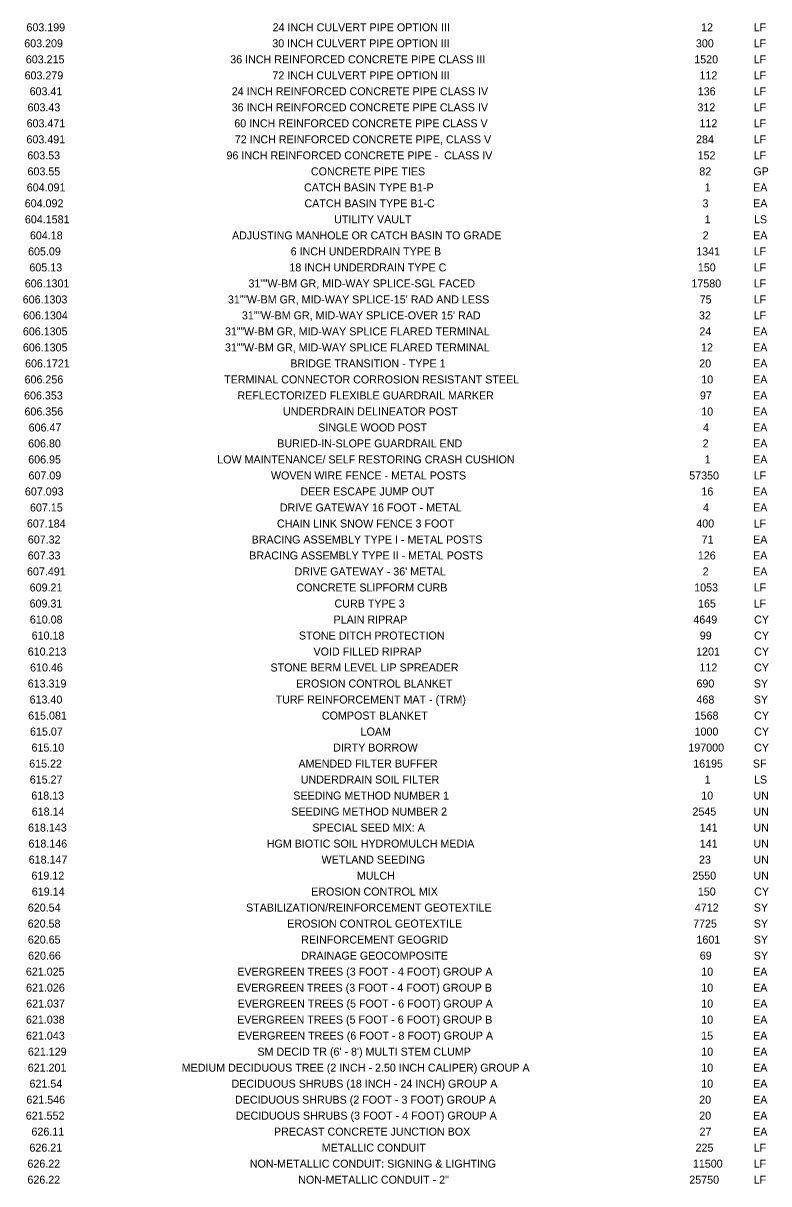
# Model space of a CAD drawing. Extents: x -18.7 to 5.6, y -2.7 to 4.
# Drawn here: x -18.674 to -17.757, y -0.273 to 1.155 of the extents above; entities that cross this region are included whole.
import ezdxf

# ---------------------------------------------------------------- set-up
doc = ezdxf.new("R2010")
doc.units = 0
doc.layers.add('ANNOTATION', color=7, linetype='Continuous')

msp = doc.modelspace()

# ---------------------------------------------------------------- texts
at = {"layer": 'ANNOTATION'}
for s, height, p in [('603.199', 0.00984, (-18.6697, 1.1446)), ('24 INCH CULVERT PIPE OPTION III', 0.009843, (-18.367, 1.1446)), ('12', 0.00984, (-17.8401, 1.1446)), ('LF', 0.00984, (-17.7755, 1.1446)), ('603.209', 0.00984, (-18.6724, 1.1249)), ('30 INCH CULVERT PIPE OPTION III', 0.009843, (-18.3674, 1.1249)), ('300', 0.00984, (-17.8465, 1.1249)), ('LF', 0.00984, (-17.7755, 1.1249)), ('603.215', 0.00984, (-18.6705, 1.1052)), ('36 INCH REINFORCED CONCRETE PIPE CLASS III', 0.009843, (-18.4191, 1.1052)), ('1520', 0.00984, (-17.8485, 1.1052)), ('LF', 0.00984, (-17.7755, 1.1052)), ('603.279', 0.00984, (-18.672, 1.0855)), ('72 INCH CULVERT PIPE OPTION III', 0.009843, (-18.3673, 1.0855)), ('112', 0.00984, (-17.8421, 1.0855)), ('LF', 0.00984, (-17.7755, 1.0855)), ('603.41', 0.00984, (-18.6658, 1.0659)), ('24 INCH REINFORCED CONCRETE PIPE CLASS IV', 0.009843, (-18.4172, 1.0659)), ('136', 0.00984, (-17.8442, 1.0659)), ('LF', 0.00984, (-17.7755, 1.0659)), ('603.43', 0.00984, (-18.6683, 1.0462)), ('36 INCH REINFORCED CONCRETE PIPE CLASS IV', 0.009843, (-18.4173, 1.0462)), ('312', 0.00984, (-17.8446, 1.0462)), ('LF', 0.00984, (-17.7755, 1.0462)), ('603.471', 0.00984, (-18.6695, 1.0265)), ('60 INCH REINFORCED CONCRETE PIPE CLASS V', 0.009843, (-18.4141, 1.0265)), ('112', 0.00984, (-17.8421, 1.0265)), ('LF', 0.00984, (-17.7755, 1.0265)), ('603.491', 0.00984, (-18.6697, 1.0068)), ('72 INCH REINFORCED CONCRETE PIPE, CLASS V', 0.009843, (-18.4135, 1.0068)), ('284', 0.00984, (-17.8463, 1.0068)), ('LF', 0.00984, (-17.7755, 1.0068)), ('603.53', 0.00984, (-18.6686, 0.9871)), ('96 INCH REINFORCED CONCRETE PIPE -  CLASS IV', 0.009843, (-18.4237, 0.9871)), ('152', 0.00984, (-17.8444, 0.9871)), ('LF', 0.00984, (-17.7755, 0.9871)), ('603.55', 0.00984, (-18.6684, 0.9674)), ('CONCRETE PIPE TIES', 0.009843, (-18.3199, 0.9674)), ('82', 0.00984, (-17.8423, 0.9674)), ('GP', 0.00984, (-17.7759, 0.9674)), ('604.091', 0.00984, (-18.6693, 0.9477)), ('CATCH BASIN TYPE B1-P', 0.009843, (-18.3284, 0.9477)), ('1', 0.00984, (-17.8358, 0.9477)), ('EA', 0.00984, (-17.7761, 0.9477)), ('604.092', 0.00984, (-18.6718, 0.9281)), ('CATCH BASIN TYPE B1-C', 0.009843, (-18.3278, 0.9281)), ('3', 0.00984, (-17.8383, 0.9281)), ('EA', 0.00984, (-17.7761, 0.9281)), ('604.1581', 0.00984, (-18.6716, 0.9084)), ('UTILITY VAULT', 0.009843, (-18.2913, 0.9084)), ('1', 0.00984, (-17.8358, 0.9084)), ('LS', 0.00984, (-17.7751, 0.9084)), ('604.18', 0.00984, (-18.6654, 0.8887)), ('ADJUSTING MANHOLE OR CATCH BASIN TO GRADE', 0.009843, (-18.4169, 0.8887)), ('2', 0.00984, (-17.8382, 0.8887)), ('EA', 0.00984, (-17.7761, 0.8887)), ('605.09', 0.00984, (-18.6677, 0.869)), ('6 INCH UNDERDRAIN TYPE B', 0.009843, (-18.3448, 0.869)), ('1341', 0.00984, (-17.8461, 0.869)), ('LF', 0.00984, (-17.7755, 0.869)), ('605.13', 0.00984, (-18.6661, 0.8493)), ('18 INCH UNDERDRAIN TYPE C', 0.009843, (-18.3464, 0.8493)), ('150', 0.00984, (-17.8441, 0.8493)), ('LF', 0.00984, (-17.7755, 0.8493)), ('606.1301', 0.00984, (-18.6718, 0.8296)), ('31””W-BM GR, MID-WAY SPLICE-SGL FACED', 0.009843, (-18.3967, 0.8296)), ('17580', 0.00984, (-17.852, 0.8296)), ('LF', 0.00984, (-17.7755, 0.8296)), ('606.1303', 0.00984, (-18.6743, 0.8099)), ("31””W-BM GR, MID-WAY SPLICE-15' RAD AND LESS", 0.009843, (-18.422, 0.8099)), ('75', 0.00984, (-17.8418, 0.8099)), ('LF', 0.00984, (-17.7755, 0.8099)), ('606.1304', 0.00984, (-18.6738, 0.7903)), ("31””W-BM GR, MID-WAY SPLICE-OVER 15' RAD", 0.009843, (-18.4048, 0.7903)), ('32', 0.00984, (-17.8427, 0.7903)), ('LF', 0.00984, (-17.7755, 0.7903)), ('606.1305', 0.00984, (-18.6741, 0.7706)), ('31””W-BM GR, MID-WAY SPLICE FLARED TERMINAL', 0.009843, (-18.4256, 0.7706)), ('24', 0.00984, (-17.8422, 0.7706)), ('EA', 0.00984, (-17.7761, 0.7706)), ('606.1305', 0.00984, (-18.6741, 0.7509)), ('31””W-BM GR, MID-WAY SPLICE FLARED TERMINAL', 0.009843, (-18.4256, 0.7509)), ('12', 0.00984, (-17.8401, 0.7509)), ('EA', 0.00984, (-17.7761, 0.7509)), ('606.1721', 0.00984, (-18.6714, 0.7312)), ('BRIDGE TRANSITION - TYPE 1', 0.009843, (-18.3452, 0.7312)), ('20', 0.00984, (-17.8424, 0.7312)), ('EA', 0.00984, (-17.7761, 0.7312)), ('606.256', 0.00984, (-18.672, 0.7115)), ('TERMINAL CONNECTOR CORROSION RESISTANT STEEL', 0.009843, (-18.4266, 0.7115)), ('10', 0.00984, (-17.8399, 0.7115)), ('EA', 0.00984, (-17.7761, 0.7115)), ('606.353', 0.00984, (-18.6726, 0.6918)), ('REFLECTORIZED FLEXIBLE GUARDRAIL MARKER', 0.009843, (-18.4102, 0.6918)), ('97', 0.00984, (-17.8415, 0.6918)), ('EA', 0.00984, (-17.7761, 0.6918)), ('606.356', 0.00984, (-18.6721, 0.6721)), ('UNDERDRAIN DELINEATOR POST', 0.009843, (-18.3543, 0.6721)), ('10', 0.00984, (-17.8399, 0.6721)), ('EA', 0.00984, (-17.7761, 0.6721)), ('606.47', 0.00984, (-18.667, 0.6524)), ('SINGLE WOOD POST', 0.009843, (-18.3109, 0.6524)), ('4', 0.00984, (-17.8378, 0.6524)), ('EA', 0.00984, (-17.7761, 0.6524)), ('606.80', 0.00984, (-18.6676, 0.6328)), ('BURIED-IN-SLOPE GUARDRAIL END', 0.009843, (-18.3613, 0.6328)), ('2', 0.00984, (-17.8382, 0.6328)), ('EA', 0.00984, (-17.7761, 0.6328)), ('606.95', 0.00984, (-18.6675, 0.6131)), ('LOW MAINTENANCE/ SELF RESTORING CRASH CUSHION', 0.009843, (-18.4351, 0.6131)), ('1', 0.00984, (-17.8358, 0.6131)), ('EA', 0.00984, (-17.7761, 0.6131)), ('607.09', 0.00984, (-18.6672, 0.5934)), ('WOVEN WIRE FENCE - METAL POSTS', 0.009843, (-18.369, 0.5934)), ('57350', 0.00984, (-17.8547, 0.5934)), ('LF', 0.00984, (-17.7755, 0.5934)), ('607.093', 0.00984, (-18.6716, 0.5737)), ('DEER ESCAPE JUMP OUT', 0.009843, (-18.3329, 0.5737)), ('16', 0.00984, (-17.8397, 0.5737)), ('EA', 0.00984, (-17.7761, 0.5737)), ('607.15', 0.00984, (-18.6653, 0.554)), ('DRIVE GATEWAY 16 FOOT - METAL', 0.009843, (-18.3581, 0.554)), ('4', 0.00984, (-17.8378, 0.554)), ('EA', 0.00984, (-17.7761, 0.554)), ('607.184', 0.00984, (-18.6691, 0.5343)), ('CHAIN LINK SNOW FENCE 3 FOOT', 0.009843, (-18.3617, 0.5343)), ('400', 0.00984, (-17.846, 0.5343)), ('LF', 0.00984, (-17.7755, 0.5343)), ('607.32', 0.00984, (-18.668, 0.5146)), ('BRACING ASSEMBLY TYPE I - METAL POSTS', 0.009843, (-18.3928, 0.5146)), ('71', 0.00984, (-17.8395, 0.5146)), ('EA', 0.00984, (-17.7761, 0.5146)), ('607.33', 0.00984, (-18.6681, 0.495)), ('BRACING ASSEMBLY TYPE II - METAL POSTS', 0.009843, (-18.3957, 0.495)), ('126', 0.00984, (-17.8441, 0.495)), ('EA', 0.00984, (-17.7761, 0.495)), ('607.491', 0.00984, (-18.669, 0.4753)), ("DRIVE GATEWAY - 36' METAL", 0.009843, (-18.34, 0.4753)), ('2', 0.00984, (-17.8382, 0.4753)), ('EA', 0.00984, (-17.7761, 0.4753)), ('609.21', 0.00984, (-18.6657, 0.4556)), ('CONCRETE SLIPFORM CURB', 0.009843, (-18.3378, 0.4556)), ('1053', 0.00984, (-17.8486, 0.4556)), ('LF', 0.00984, (-17.7755, 0.4556)), ('609.31', 0.00984, (-18.6658, 0.4359)), ('CURB TYPE 3', 0.009843, (-18.2909, 0.4359)), ('165', 0.00984, (-17.8439, 0.4359)), ('LF', 0.00984, (-17.7755, 0.4359)), ('610.08', 0.00984, (-18.6655, 0.4162)), ('PLAIN RIPRAP', 0.009843, (-18.2921, 0.4162)), ('4649', 0.00984, (-17.8496, 0.4162)), ('CY', 0.00984, (-17.7749, 0.4162)), ('610.18', 0.00984, (-18.6633, 0.3965)), ('STONE DITCH PROTECTION', 0.009843, (-18.3347, 0.3965)), ('99', 0.00984, (-17.8417, 0.3965)), ('CY', 0.00984, (-17.7749, 0.3965)), ('610.213', 0.00984, (-18.6681, 0.3768)), ('VOID FILLED RIPRAP', 0.009843, (-18.3167, 0.3768)), ('1201', 0.00984, (-17.8462, 0.3768)), ('CY', 0.00984, (-17.7749, 0.3768)), ('610.46', 0.00984, (-18.6652, 0.3572)), ('STONE BERM LEVEL LIP SPREADER', 0.009843, (-18.3696, 0.3572)), ('112', 0.00984, (-17.8421, 0.3572)), ('CY', 0.00984, (-17.7749, 0.3572)), ('613.319', 0.00984, (-18.6681, 0.3375)), ('EROSION CONTROL BLANKET', 0.009843, (-18.3381, 0.3375)), ('690', 0.00984, (-17.8458, 0.3375)), ('SY', 0.00984, (-17.7753, 0.3375)), ('613.40', 0.00984, (-18.6658, 0.3178)), ('TURF REINFORCEMENT MAT - (TRM)', 0.009843, (-18.3633, 0.3178)), ('468', 0.00984, (-17.8458, 0.3178)), ('SY', 0.00984, (-17.7753, 0.3178)), ('615.081', 0.00984, (-18.6676, 0.2981)), ('COMPOST BLANKET', 0.009843, (-18.3064, 0.2981)), ('1568', 0.00984, (-17.848, 0.2981)), ('CY', 0.00984, (-17.7749, 0.2981)), ('615.07', 0.00984, (-18.6653, 0.2784)), ('LOAM', 0.00984, (-18.2588, 0.2784)), ('1000', 0.00984, (-17.8481, 0.2784)), ('CY', 0.00984, (-17.7749, 0.2784)), ('615.10', 0.00984, (-18.6635, 0.2587)), ('DIRTY BORROW', 0.009843, (-18.2925, 0.2587)), ('197000', 0.00984, (-17.8558, 0.2587)), ('CY', 0.00984, (-17.7749, 0.2587)), ('615.22', 0.00984, (-18.6663, 0.239)), ('AMENDED FILTER BUFFER ', 0.009843, (-18.3352, 0.239)), ('16195', 0.00984, (-17.8498, 0.239)), ('SF', 0.00984, (-17.7765, 0.239)), ('615.27', 0.00984, (-18.6656, 0.2194)), ('UNDERDRAIN SOIL FILTER', 0.009843, (-18.3324, 0.2194)), ('1', 0.00984, (-17.8358, 0.2194)), ('LS', 0.00984, (-17.7751, 0.2194)), ('618.13', 0.00984, (-18.6637, 0.1997)), ('SEEDING METHOD NUMBER 1', 0.009843, (-18.3416, 0.1997)), ('10', 0.00984, (-17.8399, 0.1997)), ('UN', 0.00984, (-17.7758, 0.1997)), ('618.14', 0.00984, (-18.6632, 0.18)), ('SEEDING METHOD NUMBER 2', 0.009843, (-18.3441, 0.18)), ('2545', 0.00984, (-17.8507, 0.18)), ('UN', 0.00984, (-17.7758, 0.18)), ('618.143', 0.00984, (-18.6677, 0.1603)), ('SPECIAL SEED MIX: A', 0.009843, (-18.3181, 0.1603)), ('141', 0.00984, (-17.8417, 0.1603)), ('UN', 0.00984, (-17.7758, 0.1603)), ('618.146', 0.00984, (-18.6672, 0.1406)), ('HGM BIOTIC SOIL HYDROMULCH MEDIA', 0.009843, (-18.3742, 0.1406)), ('141', 0.00984, (-17.8417, 0.1406)), ('UN', 0.00984, (-17.7758, 0.1406)), ('618.147', 0.00984, (-18.6669, 0.1209)), ('WETLAND SEEDING', 0.009843, (-18.3068, 0.1209)), ('23', 0.00984, (-17.8427, 0.1209)), ('UN', 0.00984, (-17.7758, 0.1209)), ('619.12', 0.00984, (-18.6635, 0.1012)), ('MULCH', 0.00984, (-18.2634, 0.1012)), ('2550', 0.00984, (-17.8509, 0.1012)), ('UN', 0.00984, (-17.7758, 0.1012)), ('619.14', 0.00984, (-18.6631, 0.0816)), ('EROSION CONTROL MIX', 0.009843, (-18.3196, 0.0816)), ('150', 0.00984, (-17.8441, 0.0816)), ('CY', 0.00984, (-17.7749, 0.0816)), ('620.54', 0.00984, (-18.668, 0.0619)), ('STABILIZATION/REINFORCEMENT GEOTEXTILE', 0.009843, (-18.3997, 0.0619)), ('4712', 0.00984, (-17.8478, 0.0619)), ('SY', 0.00984, (-17.7753, 0.0619)), ('620.58', 0.00984, (-18.6681, 0.0422)), ('EROSION CONTROL GEOTEXTILE', 0.009843, (-18.349, 0.0422)), ('7725', 0.00984, (-17.8499, 0.0422)), ('SY', 0.00984, (-17.7753, 0.0422)), ('620.65', 0.00984, (-18.668, 0.0225)), ('REINFORCEMENT GEOGRID', 0.009843, (-18.3318, 0.0225)), ('1601', 0.00984, (-17.8458, 0.0225)), ('SY', 0.00984, (-17.7753, 0.0225)), ('620.66', 0.00984, (-18.6677, 0.0028)), ('DRAINAGE GEOCOMPOSITE', 0.009843, (-18.3321, 0.0028)), ('69', 0.00984, (-17.8417, 0.0028)), ('SY', 0.00984, (-17.7753, 0.0028)), ('621.025', 0.00984, (-18.6704, -0.0169)), ('EVERGREEN TREES (3 FOOT - 4 FOOT) GROUP A', 0.009843, (-18.4104, -0.0169)), ('10', 0.00984, (-17.8399, -0.0169)), ('EA', 0.00984, (-17.7761, -0.0169)), ('621.026', 0.00984, (-18.6701, -0.0366)), ('EVERGREEN TREES (3 FOOT - 4 FOOT) GROUP B', 0.009843, (-18.411, -0.0366)), ('10', 0.00984, (-17.8399, -0.0366)), ('EA', 0.00984, (-17.7761, -0.0366)), ('621.037', 0.00984, (-18.67, -0.0562)), ('EVERGREEN TREES (5 FOOT - 6 FOOT) GROUP A', 0.009843, (-18.41, -0.0562)), ('10', 0.00984, (-17.8399, -0.0562)), ('EA', 0.00984, (-17.7761, -0.0562)), ('621.038', 0.00984, (-18.6703, -0.0759)), ('EVERGREEN TREES (5 FOOT - 6 FOOT) GROUP B', 0.009843, (-18.4106, -0.0759)), ('10', 0.00984, (-17.8399, -0.0759)), ('EA', 0.00984, (-17.7761, -0.0759)), ('621.043', 0.00984, (-18.6702, -0.0956)), ('EVERGREEN TREES (6 FOOT - 8 FOOT) GROUP A', 0.009843, (-18.4097, -0.0956)), ('15', 0.00984, (-17.84, -0.0956)), ('EA', 0.00984, (-17.7761, -0.0956)), ('621.129', 0.00984, (-18.6679, -0.1153)), ("SM DECID TR (6' - 8') MULTI STEM CLUMP", 0.009843, (-18.3857, -0.1153)), ('10', 0.00984, (-17.8399, -0.1153)), ('EA', 0.00984, (-17.7761, -0.1153)), ('621.201', 0.00984, (-18.6681, -0.135)), ('MEDIUM DECIDUOUS TREE (2 INCH - 2.50 INCH CALIPER) GROUP A', 0.009843, (-18.4788, -0.135)), ('10', 0.00984, (-17.8399, -0.135)), ('EA', 0.00984, (-17.7761, -0.135)), ('621.54', 0.00984, (-18.6659, -0.1547)), ('DECIDUOUS SHRUBS (18 INCH - 24 INCH) GROUP A', 0.009843, (-18.4175, -0.1547)), ('10', 0.00984, (-17.8399, -0.1547)), ('EA', 0.00984, (-17.7761, -0.1547)), ('621.546', 0.00984, (-18.6698, -0.1744)), ('DECIDUOUS SHRUBS (2 FOOT - 3 FOOT) GROUP A', 0.009843, (-18.4133, -0.1744)), ('20', 0.00984, (-17.8424, -0.1744)), ('EA', 0.00984, (-17.7761, -0.1744)), ('621.552', 0.00984, (-18.6705, -0.194)), ('DECIDUOUS SHRUBS (3 FOOT - 4 FOOT) GROUP A', 0.009843, (-18.4124, -0.194)), ('20', 0.00984, (-17.8424, -0.194)), ('EA', 0.00984, (-17.7761, -0.194)), ('626.11', 0.00984, (-18.6635, -0.2137)), ('PRECAST CONCRETE JUNCTION BOX', 0.009843, (-18.3653, -0.2137)), ('27', 0.00984, (-17.842, -0.2137)), ('EA', 0.00984, (-17.7761, -0.2137)), ('626.21', 0.00984, (-18.666, -0.2334)), ('METALLIC CONDUIT', 0.009843, (-18.3066, -0.2334)), ('225', 0.00984, (-17.8469, -0.2334)), ('LF', 0.00984, (-17.7755, -0.2334)), ('626.22', 0.00984, (-18.6685, -0.2531)), ('NON-METALLIC CONDUIT: SIGNING & LIGHTING', 0.009843, (-18.3951, -0.2531)), ('11500', 0.00984, (-17.8502, -0.2531)), ('LF', 0.00984, (-17.7755, -0.2531)), ('626.22', 0.00984, (-18.6685, -0.2728)), ('NON-METALLIC CONDUIT - 2"', 0.009843, (-18.3355, -0.2728)), ('25750', 0.00984, (-17.8546, -0.2728)), ('LF', 0.00984, (-17.7755, -0.2728))]:
    msp.add_text(s, height=height, dxfattribs=at).set_placement(p)

doc.saveas('drawing.dxf')
